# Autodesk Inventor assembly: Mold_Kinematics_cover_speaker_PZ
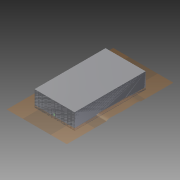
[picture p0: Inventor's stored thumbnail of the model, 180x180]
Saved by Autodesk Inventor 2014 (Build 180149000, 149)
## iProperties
Created: 2009-12
Part Number: Mold_Kinematics_cover_speaker_PZ
Document SubType Name: Assembly
Designer: gaom
Author: gaom
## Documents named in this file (9)
- C:\Users\iTools\Desktop\tutorial files\Mold\Mold Kinematics\Mold_Kinematics_cover_speaker_PZ.iam
- C:\Users\iTools\Desktop\tutorial files\Mold\Mold Kinematics\Mold_Kinematics_cover_speaker_MP.ipt
- C:\Users\iTools\Desktop\tutorial files\Mold\Mold Kinematics\Mold_Kinematics_cover_speaker_WP.ipt
- C:\Users\iTools\Desktop\tutorial files\Mold\Mold Kinematics\Mold_Kinematics_cover_speaker_CR_Base.ipt
- C:\Users\iTools\Desktop\tutorial files\Mold\Mold Kinematics\Mold_Kinematics_cover_speaker_CR_1.ipt
- C:\Users\iTools\Desktop\tutorial files\Mold\Mold Kinematics\Mold_Kinematics_cover_speaker_CV_Base.ipt
- C:\Users\iTools\Desktop\tutorial files\Mold\Mold Kinematics\Mold_Kinematics_cover_speaker_CV_1.ipt
- C:\Users\iTools\Desktop\tutorial files\Mold\Mold Kinematics\Mold_Kinematics_cover_speaker_IN1_Base.ipt
- C:\Users\iTools\Desktop\tutorial files\Mold\Mold Kinematics\Mold_Kinematics_cover_speaker_IN1_1_1.ipt
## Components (8 placed, 8 different names)
1. Mold_Kinematics_cover_speaker_MP:1 — Flush:1, Flush:2, Flush:3, Flush:4, Flush:5, Flush:6
2. Mold_Kinematics_cover_speaker_WP:1 — Flush:4, Flush:5, Flush:6
3. Mold_Kinematics_cover_speaker_CR_Base:1 — Flush:7, Flush:8, Flush:9, Flush:13, Flush:14, Flush:15
4. Mold_Kinematics_cover_speaker_CR_1:1 — Flush:13, Flush:14, Flush:15
5. Mold_Kinematics_cover_speaker_CV_Base:1 — Flush:10, Flush:11, Flush:12, Flush:16, Flush:17, Flush:18
6. Mold_Kinematics_cover_speaker_CV_1:1 — Flush:16, Flush:17, Flush:18, Flush:25, Flush:26, Flush:27
7. Mold_Kinematics_cover_speaker_IN1_Base:1 — Flush:19, Flush:20, Flush:21, Flush:22, Flush:23, Flush:24
8. Mold_Kinematics_cover_speaker_IN1_1_1:1 — Flush:22, Flush:23, Flush:24, Flush:25, Flush:26, Flush:27
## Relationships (27: Flush 27)
- Flush:1: Mold_Kinematics_cover_speaker_MP:1
- Flush:2: Mold_Kinematics_cover_speaker_MP:1
- Flush:3: Mold_Kinematics_cover_speaker_MP:1
- Flush:4: Mold_Kinematics_cover_speaker_MP:1 ↔ Mold_Kinematics_cover_speaker_WP:1
- Flush:5: Mold_Kinematics_cover_speaker_MP:1 ↔ Mold_Kinematics_cover_speaker_WP:1
- Flush:6: Mold_Kinematics_cover_speaker_MP:1 ↔ Mold_Kinematics_cover_speaker_WP:1
- Flush:7: Mold_Kinematics_cover_speaker_CR_Base:1
- Flush:8: Mold_Kinematics_cover_speaker_CR_Base:1
- Flush:9: Mold_Kinematics_cover_speaker_CR_Base:1
- Flush:10: Mold_Kinematics_cover_speaker_CV_Base:1
- Flush:11: Mold_Kinematics_cover_speaker_CV_Base:1
- Flush:12: Mold_Kinematics_cover_speaker_CV_Base:1
- Flush:13: Mold_Kinematics_cover_speaker_CR_Base:1 ↔ Mold_Kinematics_cover_speaker_CR_1:1
- Flush:14: Mold_Kinematics_cover_speaker_CR_Base:1 ↔ Mold_Kinematics_cover_speaker_CR_1:1
- Flush:15: Mold_Kinematics_cover_speaker_CR_Base:1 ↔ Mold_Kinematics_cover_speaker_CR_1:1
- Flush:16: Mold_Kinematics_cover_speaker_CV_Base:1 ↔ Mold_Kinematics_cover_speaker_CV_1:1
- Flush:17: Mold_Kinematics_cover_speaker_CV_Base:1 ↔ Mold_Kinematics_cover_speaker_CV_1:1
- Flush:18: Mold_Kinematics_cover_speaker_CV_Base:1 ↔ Mold_Kinematics_cover_speaker_CV_1:1
- Flush:19: Mold_Kinematics_cover_speaker_IN1_Base:1
- Flush:20: Mold_Kinematics_cover_speaker_IN1_Base:1
- Flush:21: Mold_Kinematics_cover_speaker_IN1_Base:1
- Flush:22: Mold_Kinematics_cover_speaker_IN1_Base:1 ↔ Mold_Kinematics_cover_speaker_IN1_1_1:1
- Flush:23: Mold_Kinematics_cover_speaker_IN1_Base:1 ↔ Mold_Kinematics_cover_speaker_IN1_1_1:1
- Flush:24: Mold_Kinematics_cover_speaker_IN1_Base:1 ↔ Mold_Kinematics_cover_speaker_IN1_1_1:1
- Flush:25: Mold_Kinematics_cover_speaker_CV_1:1 ↔ Mold_Kinematics_cover_speaker_IN1_1_1:1
- Flush:26: Mold_Kinematics_cover_speaker_CV_1:1 ↔ Mold_Kinematics_cover_speaker_IN1_1_1:1
- Flush:27: Mold_Kinematics_cover_speaker_CV_1:1 ↔ Mold_Kinematics_cover_speaker_IN1_1_1:1
